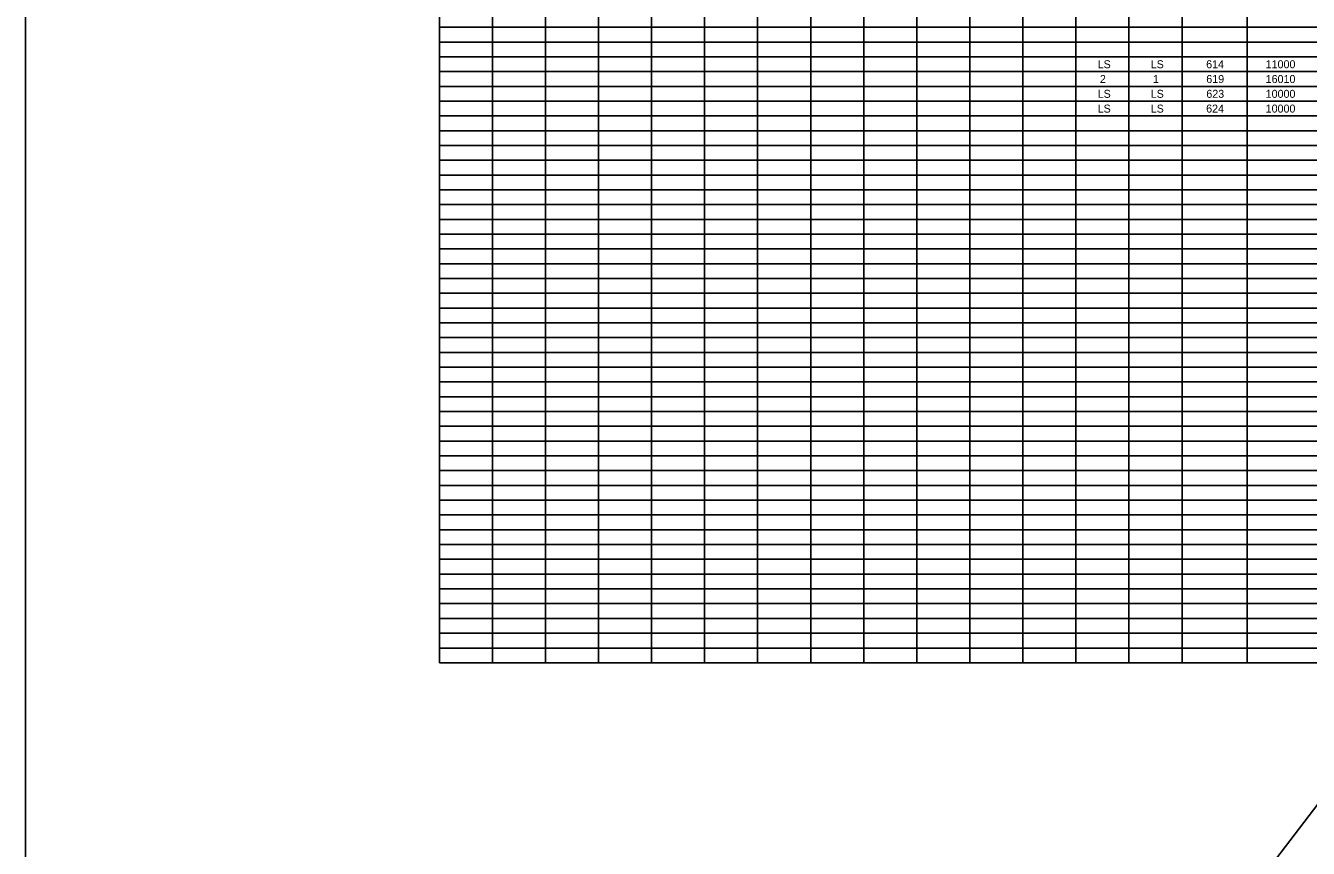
# Model space of a CAD drawing. Extents: x -53.2 to 35.8, y -26.4 to 35.9.
# Drawn here: x -53.16 to -28.86, y 4.75 to 20.33 of the extents above; entities that cross this region are included whole.
import ezdxf

# ---------------------------------------------------------------- set-up
doc = ezdxf.new("R2010")
doc.units = 0
doc.layers.add('Default', color=7, linetype='Continuous')
doc.layers.add('SC_Scratch1', color=7, linetype='Continuous')

msp = doc.modelspace()

# ---------------------------------------------------------------- linework, layer by layer
at = {"layer": 'Default'}
for p, q in [((-45.322, 29.262), (-45.322, 8.262)), ((-33.267, 29.262), (-33.267, 8.262)), ((-31.257, 29.262), (-31.257, 8.262)), ((-30.022, 29.262), (-30.022, 8.262)), ((-44.317, 28.702), (-44.317, 8.262)), ((-43.313, 28.702), (-43.313, 8.262)), ((-42.308, 28.702), (-42.308, 8.262)), ((-41.303, 28.702), (-41.303, 8.262)), ((-40.299, 28.702), (-40.299, 8.262)), ((-39.294, 28.702), (-39.294, 8.262)), ((-38.29, 28.702), (-38.29, 8.262)), ((-37.285, 28.702), (-37.285, 8.262)), ((-36.28, 28.702), (-36.28, 8.262)), ((-35.276, 28.702), (-35.276, 8.262)), ((-34.271, 28.702), (-34.271, 8.262)), ((-32.262, 28.702), (-32.262, 8.262)), ((-45.322, 20.302), (-14.822, 20.302)), ((-45.322, 20.022), (-14.822, 20.022)), ((-45.322, 19.742), (-14.822, 19.742)), ((-45.322, 19.462), (-14.822, 19.462)), ((-45.322, 19.182), (-14.822, 19.182)), ((-45.322, 18.902), (-14.822, 18.902)), ((-45.322, 18.622), (-14.822, 18.622)), ((-45.322, 18.342), (-14.822, 18.342)), ((-45.322, 18.062), (-14.822, 18.062)), ((-45.322, 17.782), (-14.822, 17.782)), ((-45.322, 17.502), (-14.822, 17.502)), ((-45.322, 17.222), (-14.822, 17.222)), ((-45.322, 16.942), (-14.822, 16.942)), ((-45.322, 16.662), (-14.822, 16.662)), ((-45.322, 16.382), (-14.822, 16.382)), ((-45.322, 16.102), (-14.822, 16.102)), ((-45.322, 15.822), (-14.822, 15.822)), ((-45.322, 15.542), (-14.822, 15.542)), ((-45.322, 15.262), (-14.822, 15.262)), ((-45.322, 14.982), (-14.822, 14.982)), ((-45.322, 14.702), (-14.822, 14.702)), ((-45.322, 14.422), (-14.822, 14.422)), ((-45.322, 14.142), (-14.822, 14.142)), ((-45.322, 13.862), (-14.822, 13.862)), ((-45.322, 13.582), (-14.822, 13.582)), ((-45.322, 13.302), (-14.822, 13.302)), ((-45.322, 13.022), (-14.822, 13.022)), ((-45.322, 12.742), (-14.822, 12.742)), ((-45.322, 12.462), (-14.822, 12.462)), ((-45.322, 12.182), (-14.822, 12.182)), ((-45.322, 11.902), (-14.822, 11.902)), ((-45.322, 11.622), (-14.822, 11.622)), ((-45.322, 11.342), (-14.822, 11.342)), ((-45.322, 11.062), (-14.822, 11.062)), ((-45.322, 10.782), (-14.822, 10.782)), ((-45.322, 10.502), (-14.822, 10.502)), ((-45.322, 10.222), (-14.822, 10.222)), ((-45.322, 9.942), (-14.822, 9.942)), ((-45.322, 9.662), (-14.822, 9.662)), ((-45.322, 9.382), (-14.822, 9.382)), ((-45.322, 9.102), (-14.822, 9.102)), ((-45.322, 8.822), (-14.822, 8.822)), ((-45.322, 8.542), (-14.822, 8.542)), ((-45.322, 8.262), (-14.822, 8.262))]:
    msp.add_line(p, q, dxfattribs=at)
at = {"layer": 'SC_Scratch1'}
msp.add_line((-53.157, -26.4), (-5.495, 35.892), dxfattribs=at)
msp.add_lwpolyline([(-53.157, 35.892), (-5.495, 35.892), (-5.495, -26.4), (-53.157, -26.4)], close=True, dxfattribs=at)

# ---------------------------------------------------------------- texts
at = {"layer": 'Default'}
for s, height, p in [('LS', 0.1515, (-32.855, 19.526)), ('LS', 0.1515, (-31.85, 19.526)), ('614', 0.1515, (-30.8, 19.526)), ('11000', 0.1515, (-29.673, 19.526)), ('2', 0.152, (-32.813, 19.246)), ('1', 0.152, (-31.808, 19.246)), ('619', 0.1515, (-30.798, 19.246)), ('16010', 0.1515, (-29.673, 19.246)), ('LS', 0.1515, (-32.855, 18.966)), ('LS', 0.1515, (-31.85, 18.966)), ('623', 0.1515, (-30.797, 18.966)), ('10000', 0.1515, (-29.673, 18.966)), ('LS', 0.1515, (-32.855, 18.686)), ('LS', 0.1515, (-31.85, 18.686)), ('624', 0.1515, (-30.8, 18.686)), ('10000', 0.1515, (-29.673, 18.686))]:
    msp.add_text(s, height=height, dxfattribs=at).set_placement(p)

doc.saveas('drawing.dxf')
